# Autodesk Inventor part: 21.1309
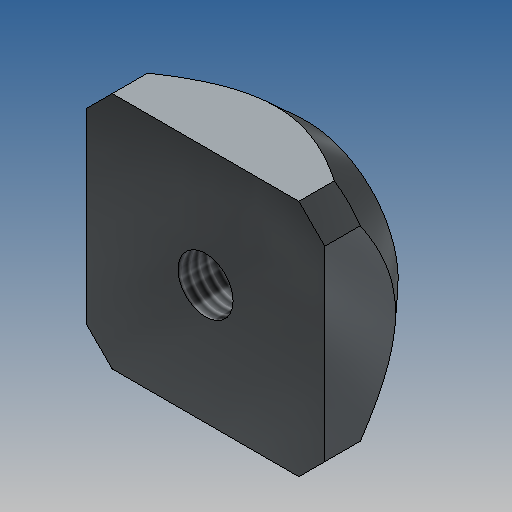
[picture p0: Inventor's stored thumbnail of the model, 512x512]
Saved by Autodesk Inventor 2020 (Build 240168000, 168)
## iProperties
Created: 2006-12
Part Number: 21.1309
Document SubType Name: Modeling
Designer: Andy Moles
Material: Steel, Mild
Density: 7.85 g/cm^3
Mass: 5.85198 g
Surface Area: 5.54896 cm^2
Volume: 0.745475 cm^3
Description: M3 SQUARE NUT
Appearance: Zinc
Author: Andy Moles
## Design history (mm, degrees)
sketch "Sketch2"
  geometry: L1 (-5.086, -6.5)-(5.086, -6.5); L2 (6.5, -5.086)-(6.5, 5.086); L3 (5.086, 6.5)-(-5.086, 6.5); L4 (-6.5, 5.086)-(-6.5, -5.086); L5 (-6.5, 6.5)-(6.5, -6.5); L6 (5.086, 6.5)-(6.5, 5.086); L7 (0, -6.5)-(0, 6.5); L8 (-6.5, 0)-(6.5, 0); L9 (-5.086, 6.5)-(-6.5, 5.086); L10 (-5.086, -6.5)-(-6.5, -5.086); L11 (5.086, -6.5)-(6.5, -5.086); C1 r 1.5 at (0, 0); 2 further points
  constraints: 22 end point, 6 symmetric about line, 4 parallel, 3 midpoint, 2 coincident, 2 perpendicular, 1 centre point, 1 horizontal
  dimensions: "THREAD" = 3 diameter of C1; "d3" = 45 deg angle of L3 L6 (derived); "d4" = 2 distance of L3.start L2.end
extrude "Extrusion1" new body sketch "Sketch2" distance "d5" = 5.5; taper "d6" = 0 deg
workplane "Work Plane1"
sketch "Sketch4"
  geometry: L1 (9.692, 0)-(6.692, 0) reference; L2 (8.192, 0)-(13.192, 0); L3 (16.385, 5.5)-(16.385, 3.5); L4 (13.192, 0)-(16.797, 3.952); L5 (13.192, 0)-(16.385, 0); L6 (16.385, 3.5)-(16.385, 0); L7 (16.797, 3.952)-(16.797, -0.412); L8 (16.797, -0.412)-(13.192, -0.412); L9 (13.192, -0.412)-(13.192, 0); L10 (8.192, 5.5)-(8.192, 0); L11 (16.385, 5.5)-(16.385, 0) reference; L12 (16.385, 3.5)-(17.502, 3.5); L13 (9.192, 5.5)-(16.385, 5.5) reference
  constraints: 20 end point, 6 perpendicular, 1 collinear, 1 midpoint, 1 parallel, 1 point on line
  dimensions: "d10" = 5 distance of L2.start L2.end; "d15" = 2 distance between parallel lines of L12 L13
revolve "Revolution1" sketch "Sketch4" stored, may be unused: angle "d12" = 90 deg
thread "Thread1" dims "d13" = 10, "d14" = 0
body "Solid1"
